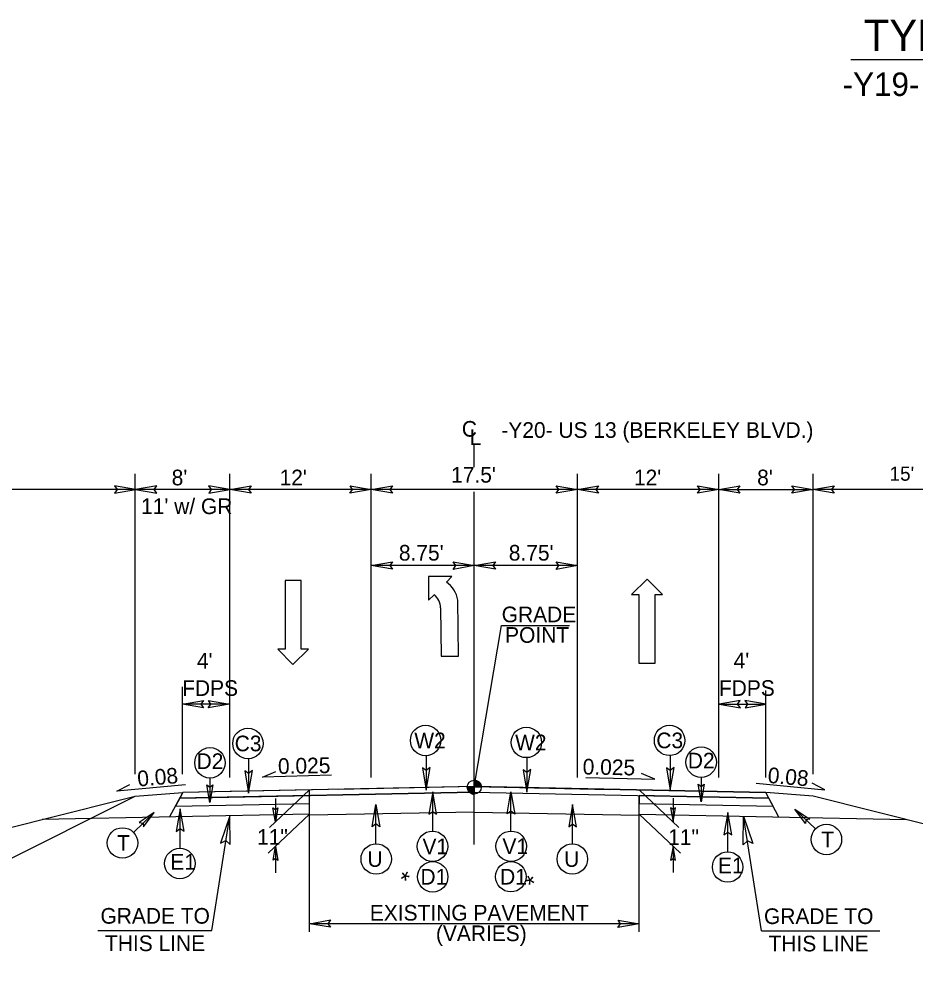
# Model space of a CAD drawing. Extents: x 2320980 to 2456309, y 595047 to 606177.
# Drawn here: x 2455789.9 to 2455866, y 595691.8 to 595772.8 of the extents above; entities that cross this region are included whole.
import ezdxf

# ---------------------------------------------------------------- set-up
doc = ezdxf.new("R2010")
doc.units = 0
for name, color, linetype in [('Old_Level_1', 7, 'Continuous'), ('Old_Level_11', 7, 'Continuous'), ('Old_Level_2', 7, 'Continuous'), ('Old_Level_20', 7, 'Continuous'), ('Old_Level_21', 7, 'Continuous'), ('Old_Level_3', 7, 'Continuous'), ('Prop Dimension', 7, 'Continuous'), ('Prop Dimension Text', 7, 'Continuous'), ('Prop Lane Arrow CELL', 7, 'Continuous'), ('Prop Terminator CELL', 7, 'Continuous'), ('Typical Grade Point Symbol CELL', 7, 'Continuous'), ('Typical Hinge Slope Arterial CELL', 7, 'Continuous'), ('Typical ID Circle CELL', 7, 'Continuous'), ('Typical Pavement Slope CELL', 7, 'Continuous'), ('Typical Pavement Slope Information CELL', 7, 'Continuous'), ('Typical Terminator CELL', 7, 'Continuous')]:
    doc.layers.add(name, color=color, linetype=linetype)

msp = doc.modelspace()

# ---------------------------------------------------------------- linework, layer by layer
at = {"layer": 'Old_Level_1'}
for p, q in [((2455828.528, 595707.615), (2455830.848, 595721.344)), ((2455830.848, 595721.344), (2455836.606, 595721.344)), ((2455814.529, 595705.312), (2455814.529, 595707.374)), ((2455842.529, 595705.315), (2455842.529, 595706.896)), ((2455828.529, 595705.502), (2455814.529, 595705.222)), ((2455814.529, 595705.222), (2455814.529, 595705.312)), ((2455828.529, 595705.502), (2455842.529, 595705.224)), ((2455842.529, 595705.224), (2455842.529, 595705.315))]:
    msp.add_line(p, q, dxfattribs=at)
at = {"layer": 'Old_Level_11'}
for points in [[(2455859.079, 595732.574), (2455857.279, 595732.884), (2455859.089, 595733.204), (2455858.859, 595732.884)], [(2455807.808, 595702.737), (2455807.769, 595705.166), (2455806.977, 595702.853), (2455807.446, 595703.09)], [(2455851.356, 595702.707), (2455851.395, 595705.136), (2455852.187, 595702.823), (2455851.719, 595703.059)]]:
    msp.add_lwpolyline(points, close=True, dxfattribs=at)
at = {"layer": 'Old_Level_21'}
for p, q in [((2455799.748, 595708.721), (2455799.748, 595734.214)), ((2455807.779, 595708.426), (2455807.779, 595734.214)), ((2455819.779, 595708.426), (2455819.779, 595734.214)), ((2455837.279, 595708.426), (2455837.279, 595734.214)), ((2455849.279, 595708.426), (2455849.279, 595734.214)), ((2455857.311, 595708.724), (2455857.311, 595734.214)), ((2455799.779, 595732.884), (2455769.779, 595732.884)), ((2455807.779, 595732.884), (2455799.779, 595732.884)), ((2455819.779, 595732.884), (2455807.779, 595732.884)), ((2455837.279, 595732.884), (2455819.779, 595732.884)), ((2455849.279, 595732.884), (2455837.279, 595732.884)), ((2455849.279, 595732.884), (2455857.279, 595732.884)), ((2455828.529, 595726.426), (2455819.779, 595726.426)), ((2455837.279, 595726.426), (2455828.529, 595726.426)), ((2455803.748, 595708.721), (2455803.748, 595716.121)), ((2455803.748, 595708.721), (2455803.748, 595715.996)), ((2455853.279, 595708.426), (2455853.279, 595715.829)), ((2455807.748, 595714.658), (2455803.748, 595714.658)), ((2455849.311, 595714.66), (2455853.311, 595714.66)), ((2455806.255, 595695.45), (2455807.769, 595705.166)), ((2455814.529, 595695.334), (2455814.529, 595705.222)), ((2455842.529, 595695.334), (2455842.529, 595705.224)), ((2455852.909, 595695.422), (2455851.395, 595705.136)), ((2455842.529, 595696.019), (2455814.529, 595696.019)), ((2455796.577, 595695.45), (2455806.255, 595695.45)), ((2455852.909, 595695.422), (2455862.946, 595695.422))]:
    msp.add_line(p, q, dxfattribs=at)
at = {"layer": 'Old_Level_3'}
msp.add_line((2455860.483, 595769.405), (2455905.403, 595769.405), dxfattribs=at)
at = {"layer": 'Prop Dimension'}
for p, q in [((2455872.279, 595732.884), (2455857.279, 595732.884)), ((2455814.529, 595707.374), (2455811.152, 595704.191)), ((2455842.529, 595707.378), (2455845.907, 595704.195)), ((2455811.653, 595706.663), (2455811.653, 595704.663)), ((2455845.406, 595706.666), (2455845.406, 595704.667)), ((2455814.529, 595705.311), (2455811.025, 595702.009)), ((2455842.529, 595705.315), (2455846.034, 595702.012)), ((2455811.653, 595702.6), (2455811.653, 595700.349)), ((2455845.406, 595702.604), (2455845.406, 595700.353))]:
    msp.add_line(p, q, dxfattribs=at)
at = {"layer": 'Prop Dimension Text'}
for p, q in [((2455828.529, 595734.779), (2455828.529, 595736.66)), ((2455828.529, 595722.6), (2455828.529, 595732.686)), ((2455828.529, 595702.73), (2455828.529, 595722.6)), ((2455806.088, 595708.39), (2455806.088, 595706.307)), ((2455847.79, 595708.44), (2455847.79, 595706.357)), ((2455857.489, 595704.067), (2455855.731, 595705.748)), ((2455799.601, 595703.769), (2455801.359, 595705.45))]:
    msp.add_line(p, q, dxfattribs=at)
for points in [[(2455816.408, 595708.623), (2455810.552, 595708.462), (2455811.689, 595708.95)], [(2455838.011, 595708.442), (2455843.867, 595708.281), (2455842.73, 595708.77)], [(2455804.01, 595707.812), (2455798.177, 595707.263), (2455799.279, 595707.826)], [(2455852.47, 595707.943), (2455858.302, 595707.394), (2455857.2, 595707.957)]]:
    msp.add_lwpolyline(points, dxfattribs=at)
for centre in [(2455809.316, 595711.324), (2455824.396, 595711.58), (2455832.953, 595711.412), (2455845.109, 595711.583), (2455806.088, 595709.683), (2455847.791, 595709.733), (2455798.666, 595702.876), (2455858.424, 595703.173), (2455824.979, 595702.587), (2455831.659, 595702.594), (2455803.536, 595701.13), (2455820.206, 595701.512), (2455836.853, 595701.512), (2455850.035, 595700.831), (2455825.001, 595700.002), (2455831.637, 595700.009)]:
    msp.add_circle(centre, 1.293, dxfattribs=at)
at = {"layer": 'Prop Lane Arrow CELL'}
for p, q in [((2455812.463, 595725.15), (2455812.463, 595719.331)), ((2455813.835, 595725.15), (2455812.463, 595725.15)), ((2455813.835, 595719.331), (2455813.835, 595725.15)), ((2455826.624, 595725.51), (2455824.644, 595725.504)), ((2455824.644, 595725.504), (2455824.651, 595723.479)), ((2455826.159, 595725.031), (2455826.624, 595725.51)), ((2455843.215, 595725.27), (2455841.885, 595723.961)), ((2455844.504, 595723.961), (2455843.215, 595725.27)), ((2455824.651, 595723.479), (2455825.117, 595723.958)), ((2455827.196, 595718.745), (2455827.126, 595723.492)), ((2455841.885, 595723.961), (2455842.509, 595723.961)), ((2455842.509, 595723.961), (2455842.509, 595718.142)), ((2455843.88, 595718.142), (2455843.88, 595723.961)), ((2455843.88, 595723.961), (2455844.504, 595723.961)), ((2455825.651, 595722.841), (2455825.711, 595718.724)), ((2455812.463, 595719.331), (2455811.84, 595719.331)), ((2455811.84, 595719.331), (2455813.128, 595718.022)), ((2455813.128, 595718.022), (2455814.458, 595719.331)), ((2455814.458, 595719.331), (2455813.835, 595719.331)), ((2455825.711, 595718.724), (2455827.196, 595718.745)), ((2455842.509, 595718.142), (2455843.88, 595718.142))]:
    msp.add_line(p, q, dxfattribs=at)
for centre, radius, start, end in [((2455824.803, 595723.102), 2.364, 9.51716, 54.82885), ((2455824.185, 595722.824), 1.474, 0.84109, 50.49926)]:
    msp.add_arc(centre, radius, start, end, dxfattribs=at)
at = {"layer": 'Prop Terminator CELL'}
for points in [[(2455811.859, 595705.86), (2455811.653, 595704.663), (2455811.44, 595705.867), (2455811.653, 595705.714)], [(2455845.2, 595705.864), (2455845.406, 595704.667), (2455845.619, 595705.87), (2455845.406, 595705.717)], [(2455811.446, 595701.403), (2455811.653, 595702.6), (2455811.865, 595701.397), (2455811.653, 595701.55)], [(2455845.612, 595701.407), (2455845.406, 595702.604), (2455845.193, 595701.4), (2455845.406, 595701.553)]]:
    msp.add_lwpolyline(points, close=True, dxfattribs=at)
at = {"layer": 'Typical Grade Point Symbol CELL'}
for p, q in [((2455828.528, 595707.615), (2455828.528, 595708.21)), ((2455827.933, 595707.615), (2455828.528, 595707.615)), ((2455828.527, 595707.02), (2455828.528, 595707.615)), ((2455828.528, 595707.615), (2455828.527, 595707.02)), ((2455829.123, 595707.615), (2455828.528, 595707.615))]:
    msp.add_line(p, q, dxfattribs=at)
for points in [[(2455828.533, 595708.21), (2455828.533, 595708.21), (2455828.533, 595707.615)], [(2455828.545, 595708.21), (2455828.545, 595707.615)], [(2455828.557, 595708.209), (2455828.557, 595707.615)], [(2455828.569, 595708.209), (2455828.569, 595707.615)], [(2455828.581, 595708.208), (2455828.581, 595707.615)], [(2455828.593, 595708.206), (2455828.593, 595707.615)], [(2455828.605, 595708.205), (2455828.605, 595707.615)], [(2455828.617, 595708.204), (2455828.617, 595707.615)], [(2455828.629, 595708.203), (2455828.629, 595707.615)], [(2455828.641, 595708.2), (2455828.641, 595707.615)], [(2455828.653, 595708.197), (2455828.653, 595707.615)], [(2455828.664, 595708.195), (2455828.664, 595707.615)], [(2455828.676, 595708.192), (2455828.676, 595707.615)], [(2455828.688, 595708.188), (2455828.688, 595707.615)], [(2455828.7, 595708.185), (2455828.7, 595707.615)], [(2455828.712, 595708.181), (2455828.712, 595707.615)], [(2455828.724, 595708.177), (2455828.724, 595707.615)], [(2455828.736, 595708.173), (2455828.736, 595707.615)], [(2455828.748, 595708.168), (2455828.748, 595707.615)], [(2455828.76, 595708.163), (2455828.76, 595707.615)], [(2455828.772, 595708.158), (2455828.772, 595707.615)], [(2455828.783, 595708.152), (2455828.783, 595707.615)], [(2455828.795, 595708.147), (2455828.795, 595707.615)], [(2455828.807, 595708.14), (2455828.807, 595707.615)], [(2455828.819, 595708.134), (2455828.819, 595707.615)], [(2455828.831, 595708.127), (2455828.831, 595707.615)], [(2455828.843, 595708.121), (2455828.843, 595707.615)], [(2455828.855, 595708.113), (2455828.855, 595707.615)], [(2455828.867, 595708.105), (2455828.867, 595707.615)], [(2455828.879, 595708.095), (2455828.879, 595707.615)], [(2455828.891, 595708.087), (2455828.891, 595707.615)], [(2455828.903, 595708.078), (2455828.903, 595707.615)], [(2455828.914, 595708.068), (2455828.914, 595707.615)], [(2455828.926, 595708.057), (2455828.926, 595707.615)], [(2455828.938, 595708.046), (2455828.938, 595707.615)], [(2455827.936, 595707.615), (2455827.936, 595707.55)], [(2455827.947, 595707.615), (2455827.947, 595707.48)], [(2455827.959, 595707.615), (2455827.959, 595707.438)], [(2455827.971, 595707.615), (2455827.971, 595707.402)], [(2455827.983, 595707.615), (2455827.983, 595707.374)], [(2455827.995, 595707.615), (2455827.995, 595707.349)], [(2455828.007, 595707.615), (2455828.007, 595707.327)], [(2455828.019, 595707.615), (2455828.019, 595707.306)], [(2455828.031, 595707.615), (2455828.031, 595707.287)], [(2455828.043, 595707.615), (2455828.043, 595707.27)], [(2455828.055, 595707.615), (2455828.055, 595707.254)], [(2455828.066, 595707.615), (2455828.066, 595707.239)], [(2455828.078, 595707.615), (2455828.078, 595707.225)], [(2455828.09, 595707.615), (2455828.09, 595707.212)], [(2455828.102, 595707.615), (2455828.102, 595707.198)], [(2455828.114, 595707.615), (2455828.114, 595707.187)], [(2455828.126, 595707.615), (2455828.126, 595707.176)], [(2455828.138, 595707.615), (2455828.138, 595707.165)], [(2455828.15, 595707.615), (2455828.15, 595707.155)], [(2455828.162, 595707.615), (2455828.162, 595707.146)], [(2455828.174, 595707.615), (2455828.174, 595707.136)], [(2455828.185, 595707.615), (2455828.185, 595707.128)], [(2455828.197, 595707.615), (2455828.197, 595707.12)], [(2455828.209, 595707.615), (2455828.209, 595707.112)], [(2455828.221, 595707.615), (2455828.221, 595707.105)], [(2455828.233, 595707.615), (2455828.233, 595707.098)], [(2455828.245, 595707.615), (2455828.245, 595707.091)], [(2455828.257, 595707.615), (2455828.257, 595707.085)], [(2455828.269, 595707.615), (2455828.269, 595707.079)], [(2455828.281, 595707.615), (2455828.281, 595707.074)], [(2455828.293, 595707.615), (2455828.293, 595707.069)], [(2455828.305, 595707.615), (2455828.305, 595707.064)], [(2455828.316, 595707.615), (2455828.316, 595707.058)], [(2455828.328, 595707.615), (2455828.328, 595707.054)], [(2455828.34, 595707.615), (2455828.34, 595707.05)], [(2455828.352, 595707.615), (2455828.352, 595707.046)], [(2455828.364, 595707.615), (2455828.364, 595707.044)], [(2455828.376, 595707.615), (2455828.376, 595707.04)], [(2455828.388, 595707.615), (2455828.388, 595707.037)], [(2455828.4, 595707.615), (2455828.4, 595707.034)], [(2455828.412, 595707.615), (2455828.412, 595707.032)], [(2455828.424, 595707.615), (2455828.424, 595707.029)], [(2455828.436, 595707.615), (2455828.436, 595707.028)], [(2455828.447, 595707.615), (2455828.447, 595707.025)], [(2455828.459, 595707.615), (2455828.459, 595707.024)], [(2455828.471, 595707.615), (2455828.471, 595707.023)], [(2455828.483, 595707.615), (2455828.483, 595707.021)], [(2455828.495, 595707.615), (2455828.495, 595707.021)], [(2455828.507, 595707.615), (2455828.507, 595707.02)], [(2455828.519, 595707.615), (2455828.519, 595707.02), (2455828.519, 595707.02)], [(2455828.95, 595708.035), (2455828.95, 595707.615)], [(2455828.962, 595708.023), (2455828.962, 595707.615)], [(2455828.974, 595708.009), (2455828.974, 595707.615)], [(2455828.986, 595707.995), (2455828.986, 595707.615)], [(2455828.998, 595707.98), (2455828.998, 595707.615)], [(2455829.01, 595707.964), (2455829.01, 595707.615)], [(2455829.022, 595707.947), (2455829.022, 595707.615)], [(2455829.034, 595707.929), (2455829.034, 595707.615)], [(2455829.045, 595707.909), (2455829.045, 595707.615)], [(2455829.057, 595707.888), (2455829.057, 595707.615)], [(2455829.069, 595707.863), (2455829.069, 595707.615)], [(2455829.081, 595707.835), (2455829.081, 595707.615)], [(2455829.093, 595707.802), (2455829.093, 595707.615)], [(2455829.105, 595707.761), (2455829.105, 595707.615)], [(2455829.117, 595707.7), (2455829.117, 595707.615)]]:
    msp.add_lwpolyline(points, dxfattribs=at)
msp.add_circle((2455828.527, 595707.615), 0.595, dxfattribs=at)
for start, end in [(359.99048, 89.99048), (179.99048, 269.99048)]:
    msp.add_arc((2455828.527, 595707.615), 0.595, start, end, dxfattribs=at)
at = {"layer": 'Typical Hinge Slope Arterial CELL'}
for p, q in [((2455769.753, 595691.838), (2455799.748, 595706.836)), ((2455791.84, 595704.859), (2455799.748, 595706.836)), ((2455872.311, 595703.089), (2455857.311, 595706.839)), ((2455769.748, 595699.336), (2455791.84, 595704.859))]:
    msp.add_line(p, q, dxfattribs=at)
at = {"layer": 'Typical ID Circle CELL'}
for p, q in [((2455809.367, 595710.052), (2455809.367, 595707.111)), ((2455824.447, 595710.308), (2455824.447, 595707.367)), ((2455833.004, 595710.14), (2455833.004, 595707.2)), ((2455845.16, 595710.31), (2455845.16, 595707.37)), ((2455831.634, 595703.892), (2455831.634, 595707.23)), ((2455825.004, 595703.885), (2455825.004, 595707.223)), ((2455803.561, 595702.428), (2455803.561, 595705.766)), ((2455820.18, 595702.81), (2455820.18, 595706.148)), ((2455836.878, 595702.81), (2455836.878, 595706.148)), ((2455850.061, 595702.128), (2455850.061, 595705.467))]:
    msp.add_line(p, q, dxfattribs=at)
at = {"layer": 'Typical Pavement Slope CELL'}
for p, q in [((2455828.546, 595707.656), (2455803.779, 595707.158)), ((2455807.803, 595707.239), (2455803.779, 595707.158)), ((2455828.546, 595707.656), (2455807.803, 595707.239)), ((2455828.529, 595707.666), (2455817.029, 595707.404)), ((2455828.546, 595707.656), (2455828.454, 595707.178)), ((2455828.454, 595707.178), (2455828.546, 595707.656)), ((2455828.529, 595707.668), (2455840.029, 595707.406)), ((2455828.546, 595707.656), (2455853.279, 595707.161)), ((2455853.279, 595707.161), (2455828.546, 595707.656)), ((2455799.748, 595706.836), (2455803.779, 595707.158)), ((2455802.664, 595705.075), (2455803.779, 595707.158)), ((2455803.522, 595706.677), (2455803.154, 595705.991)), ((2455828.454, 595707.178), (2455803.522, 595706.677)), ((2455814.529, 595706.895), (2455803.522, 595706.677)), ((2455810.237, 595706.81), (2455803.522, 595706.677)), ((2455810.335, 595706.812), (2455810.237, 595706.81)), ((2455814.529, 595706.895), (2455810.335, 595706.812)), ((2455814.529, 595706.215), (2455814.529, 595706.895)), ((2455828.454, 595707.178), (2455853.539, 595706.676)), ((2455828.454, 595707.178), (2455853.539, 595706.676)), ((2455846.438, 595706.816), (2455842.529, 595706.894)), ((2455842.529, 595706.894), (2455842.529, 595706.214)), ((2455846.543, 595706.814), (2455846.438, 595706.816)), ((2455853.539, 595706.676), (2455846.543, 595706.814)), ((2455853.539, 595706.676), (2455853.279, 595707.161)), ((2455857.311, 595706.839), (2455853.279, 595707.161)), ((2455854.395, 595705.078), (2455853.279, 595707.161)), ((2455853.907, 595705.99), (2455853.539, 595706.676)), ((2455803.154, 595705.991), (2455814.529, 595706.215)), ((2455842.529, 595706.214), (2455853.907, 595705.99)), ((2455814.529, 595705.312), (2455791.84, 595704.859)), ((2455842.529, 595705.315), (2455865.219, 595704.862))]:
    msp.add_line(p, q, dxfattribs=at)
msp.add_lwpolyline([(2455803.779, 595707.158), (2455803.522, 595706.677), (2455828.454, 595707.178)], dxfattribs=at)
at = {"layer": 'Typical Terminator CELL'}
for points in [[(2455797.984, 595732.575), (2455799.779, 595732.884), (2455797.974, 595733.204), (2455798.203, 595732.884)], [(2455801.575, 595733.194), (2455799.779, 595732.884), (2455801.585, 595732.565), (2455801.355, 595732.884)], [(2455805.984, 595732.575), (2455807.779, 595732.884), (2455805.974, 595733.204), (2455806.203, 595732.884)], [(2455809.575, 595732.575), (2455807.779, 595732.884), (2455809.585, 595733.204), (2455809.355, 595732.884)], [(2455817.984, 595733.194), (2455819.779, 595732.884), (2455817.974, 595732.565), (2455818.203, 595732.884)], [(2455821.575, 595732.575), (2455819.779, 595732.884), (2455821.585, 595733.204), (2455821.355, 595732.884)], [(2455835.484, 595733.194), (2455837.279, 595732.884), (2455835.474, 595732.565), (2455835.703, 595732.884)], [(2455839.075, 595732.575), (2455837.279, 595732.884), (2455839.085, 595733.204), (2455838.855, 595732.884)], [(2455847.484, 595733.194), (2455849.279, 595732.884), (2455847.474, 595732.565), (2455847.703, 595732.884)], [(2455851.075, 595732.575), (2455849.279, 595732.884), (2455851.085, 595733.204), (2455850.855, 595732.884)], [(2455855.484, 595733.194), (2455857.279, 595732.884), (2455855.474, 595732.565), (2455855.703, 595732.884)], [(2455821.575, 595726.117), (2455819.779, 595726.426), (2455821.585, 595726.745), (2455821.355, 595726.426)], [(2455826.734, 595726.735), (2455828.529, 595726.426), (2455826.724, 595726.107), (2455826.953, 595726.426)], [(2455830.325, 595726.117), (2455828.529, 595726.426), (2455830.335, 595726.745), (2455830.105, 595726.426)], [(2455835.484, 595726.735), (2455837.279, 595726.426), (2455835.474, 595726.107), (2455835.703, 595726.426)], [(2455805.543, 595714.348), (2455803.748, 595714.658), (2455805.553, 595714.977), (2455805.324, 595714.658)], [(2455805.952, 595714.967), (2455807.748, 595714.658), (2455805.943, 595714.338), (2455806.172, 595714.658)], [(2455851.106, 595714.97), (2455849.311, 595714.66), (2455851.116, 595714.341), (2455850.887, 595714.66)], [(2455851.515, 595714.351), (2455853.311, 595714.66), (2455851.505, 595714.979), (2455851.735, 595714.66)], [(2455809.04, 595709.006), (2455809.367, 595707.111), (2455809.704, 595709.017), (2455809.367, 595708.774)], [(2455824.12, 595709.262), (2455824.447, 595707.367), (2455824.784, 595709.272), (2455824.447, 595709.03)], [(2455832.678, 595709.094), (2455833.004, 595707.2), (2455833.341, 595709.105), (2455833.004, 595708.863)], [(2455844.833, 595709.265), (2455845.16, 595707.37), (2455845.497, 595709.275), (2455845.16, 595709.033)], [(2455806.346, 595707.804), (2455806.088, 595706.307), (2455805.822, 595707.812), (2455806.088, 595707.621)], [(2455831.307, 595705.335), (2455831.634, 595707.23), (2455831.971, 595705.324), (2455831.634, 595705.566)], [(2455848.048, 595707.854), (2455847.79, 595706.357), (2455847.524, 595707.862), (2455847.79, 595707.671)], [(2455825.331, 595705.328), (2455825.004, 595707.223), (2455824.667, 595705.317), (2455825.004, 595705.559)], [(2455803.888, 595703.871), (2455803.561, 595705.766), (2455803.224, 595703.861), (2455803.561, 595704.103)], [(2455819.854, 595704.253), (2455820.18, 595706.148), (2455820.517, 595704.243), (2455820.18, 595704.485)], [(2455837.205, 595704.253), (2455836.878, 595706.148), (2455836.542, 595704.243), (2455836.878, 595704.485)], [(2455856.634, 595704.527), (2455855.731, 595705.748), (2455857.002, 595704.9), (2455856.68, 595704.84)], [(2455800.456, 595704.23), (2455801.359, 595705.45), (2455800.088, 595704.602), (2455800.41, 595704.542)], [(2455850.387, 595703.572), (2455850.061, 595705.467), (2455849.724, 595703.561), (2455850.061, 595703.803)], [(2455816.325, 595695.71), (2455814.529, 595696.019), (2455816.335, 595696.338), (2455816.105, 595696.019)], [(2455840.734, 595696.328), (2455842.529, 595696.019), (2455840.724, 595695.7), (2455840.953, 595696.019)]]:
    msp.add_lwpolyline(points, close=True, dxfattribs=at)

# ---------------------------------------------------------------- texts
at = {"layer": 'Old_Level_1'}
for s, p in [('GRADE', (2455830.856, 595721.615)), ('POINT', (2455831.146, 595719.872))]:
    msp.add_text(s, height=1.33, dxfattribs=at).set_placement(p)
at = {"layer": 'Old_Level_2'}
for s, height, p in [('TYPICAL SECTION No. 17', 2.66, (2455861.587, 595770.138)), ('-Y19- STA. 10+00.00 TO 13+79.15', 1.995, (2455859.798, 595766.306))]:
    msp.add_text(s, height=height, dxfattribs=at).set_placement(p)
at = {"layer": 'Old_Level_20'}
for s, p in [('W2', (2455823.438, 595710.915)), ('W2', (2455831.995, 595710.747)), ('C3', (2455843.984, 595710.918)), ('C3', (2455808.191, 595710.659)), ('T', (2455798.205, 595702.211)), ('V1', (2455824.134, 595701.922)), ('V1', (2455830.92, 595701.929)), ('T', (2455857.987, 595702.508)), ('E1', (2455802.725, 595700.601)), ('U', (2455819.464, 595700.847)), ('U', (2455836.161, 595700.847)), ('E1', (2455849.224, 595700.302)), ('D1', (2455823.96, 595699.337)), ('D1', (2455830.721, 595699.344))]:
    msp.add_text(s, height=1.33, dxfattribs=at).set_placement(p)
for p in [(2455804.954, 595709.154), (2455846.657, 595709.204)]:
    msp.add_text('D2', height=1.33, rotation=359.99718, dxfattribs=at).set_placement(p)
at = {"layer": 'Old_Level_21'}
for s, rotation, p in [('C', 0.00016, (2455827.47, 595737.376)), ('L', 0.00016, (2455828.13, 595736.66)), ("4'", 359.99984, (2455804.983, 595717.689)), ("4'", 359.99984, (2455850.546, 595717.692)), ('FDPS', 359.99984, (2455803.732, 595715.362)), ('FDPS', 359.99984, (2455849.295, 595715.364)), ('0.025', 1.14561, (2455811.876, 595708.728)), ('0.025', 358.85439, (2455837.723, 595708.695)), ('0.08', 4.95402, (2455799.98, 595707.66)), ('0.08', 355.04598, (2455853.4, 595707.983))]:
    msp.add_text(s, height=1.33, rotation=rotation, dxfattribs=at).set_placement(p)
for s, p in [('-Y20- US 13 (BERKELEY BLVD.)', (2455830.828, 595737.275)), ("17.5'", (2455826.563, 595733.473)), ("8'", (2455802.841, 595733.243)), ("12'", (2455812.001, 595733.243)), ("12'", (2455842.083, 595733.243)), ("8'", (2455852.543, 595733.243)), ("11' w/ GR", (2455800.242, 595730.802)), ("8.75'", (2455822.129, 595726.852)), ("8.75'", (2455831.459, 595726.852)), ('EXISTING PAVEMENT', (2455819.661, 595696.281)), ('GRADE TO', (2455796.795, 595696.02)), ('GRADE TO', (2455853.124, 595695.991)), ('(VARIES)', (2455825.273, 595694.538)), ('THIS LINE', (2455797.181, 595693.692)), ('THIS LINE', (2455853.511, 595693.664))]:
    msp.add_text(s, height=1.33, dxfattribs=at).set_placement(p)
at = {"layer": 'Prop Dimension Text'}
msp.add_text("15'", height=1.2, rotation=0.00016, dxfattribs=at).set_placement((2455863.784, 595733.633))
at = {"layer": 'Typical Pavement Slope CELL'}
for rotation, p in [(333.43407, (2455821.826, 595699.254)), (26.56593, (2455833.4, 595698.555))]:
    msp.add_text('*', height=1.496, rotation=rotation, dxfattribs=at).set_placement(p)
at = {"layer": 'Typical Pavement Slope Information CELL'}
for p in [(2455810.092, 595702.717), (2455844.99, 595702.709)]:
    msp.add_text('11"', height=1.33, dxfattribs=at).set_placement(p)

doc.saveas('drawing.dxf')
